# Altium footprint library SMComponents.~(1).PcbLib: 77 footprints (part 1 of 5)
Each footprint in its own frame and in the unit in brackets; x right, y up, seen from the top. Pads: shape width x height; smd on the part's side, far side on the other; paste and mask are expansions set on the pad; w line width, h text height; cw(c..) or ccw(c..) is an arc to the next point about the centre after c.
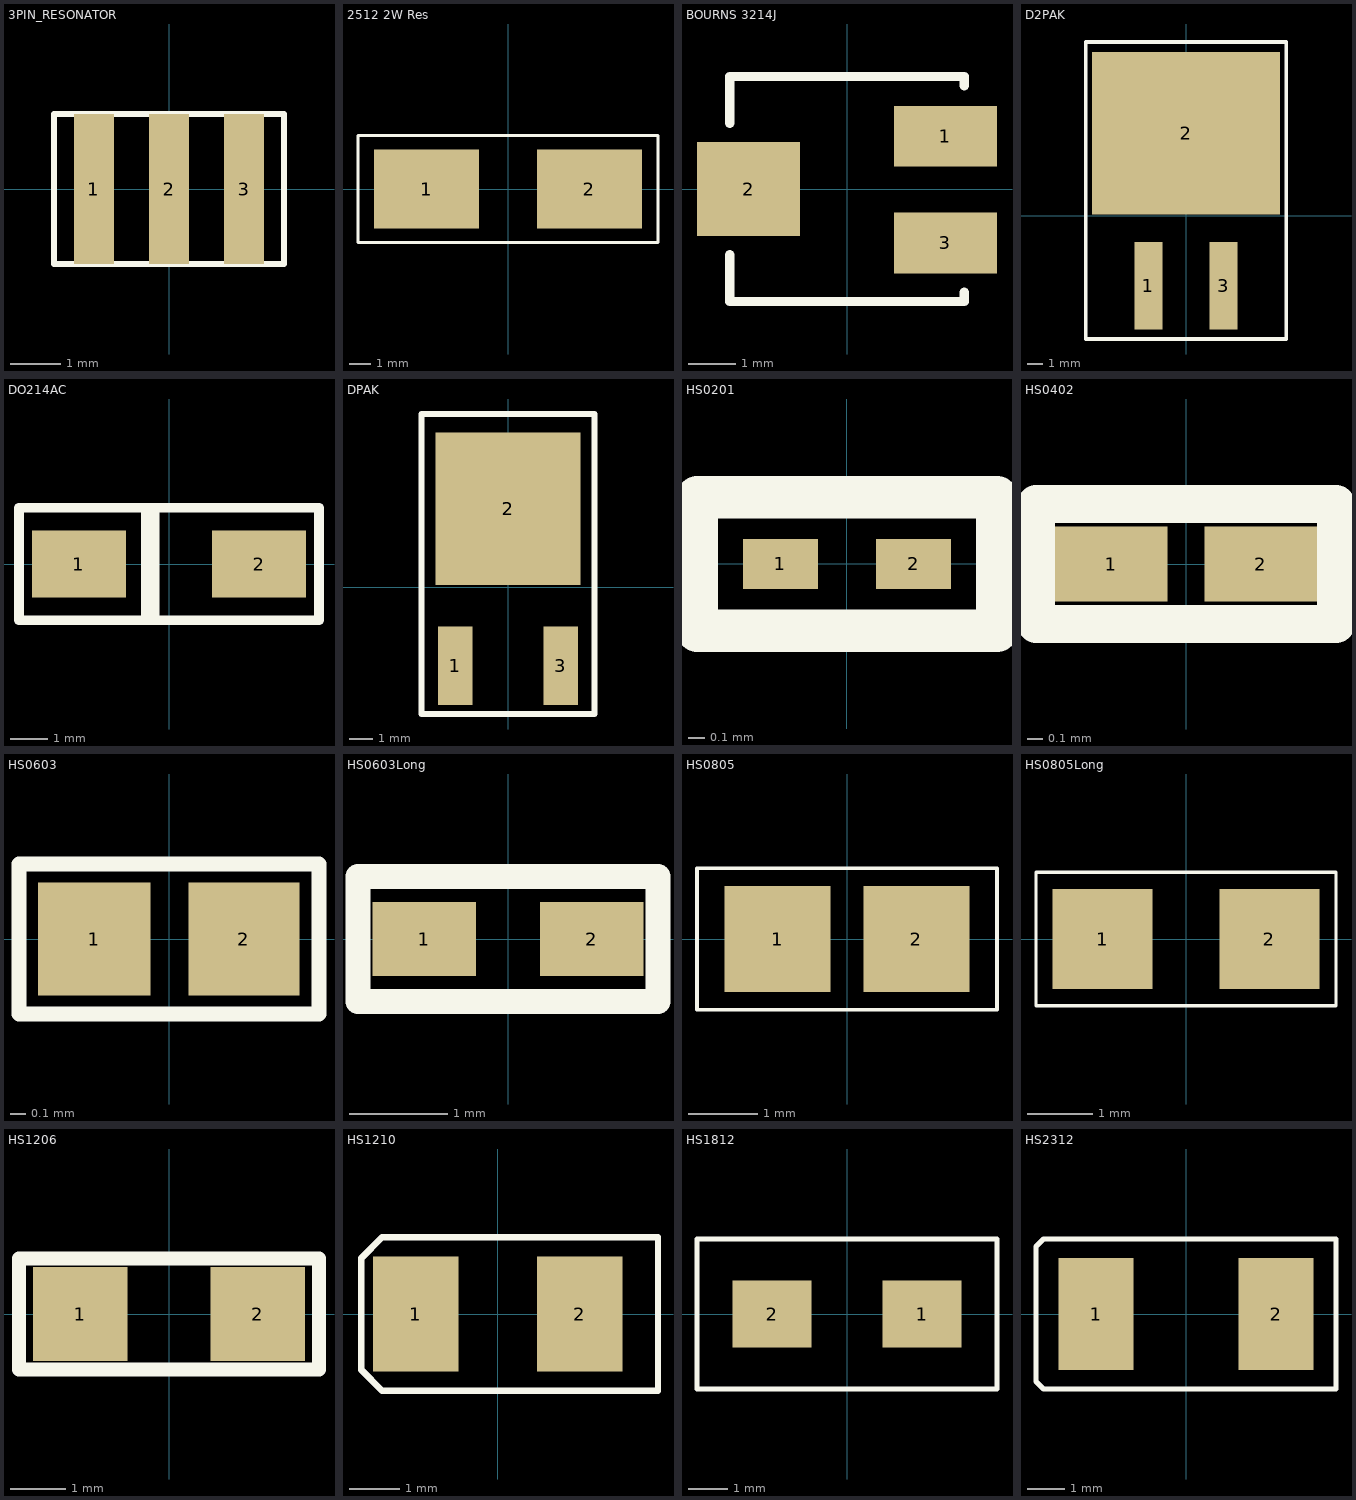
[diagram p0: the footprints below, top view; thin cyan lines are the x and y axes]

## 3PIN_RESONATOR [mm] "Mutata 600 series"
height 1.2
pads (3):
  rect 0.8x3 smd: 1(-1.5,0) 2(0,0) 3(1.5,0)
Top Overlay:
  lines w0.127: -2.3,-1.5 2.3,-1.5 2.3,1.5 -2.3,1.5 -2.3,-1.5

## 2512 2W Res [mm] "2W power resistor"
height 1
pads (2):
  rect 4.9x3.7 smd: 1(-3.8,0) 2(3.8,0)
Top Overlay:
  lines w0.127: -7,-2.5 -7,2.5 7,2.5 7,-2.5 -7,-2.5

## BOURNS 3214J [mm] "Bourns 3214J sm trimpot"
pads (3):
  rect 2.2x1.3 smd: 1(2.1,1.125) 3(2.1,-1.15)
  rect 2.2x2 smd: 2(-2.1,0)
Top Overlay:
  lines w0.2: -2.5,-1.4 -2.5,-2.4 2.5,-2.4 2.5,-2.2 ; -2.5,1.4 -2.5,2.4 2.5,2.4 2.5,2.2

## D2PAK [mm] "D2PAK 3 terminal (Will also mount DPAK)"
height 4
pads (3):
  rect 1.81x5.675 smd: 1(-2.435,-4.537) 3(2.435,-4.537)
  rect 12.2x10.525 smd: 2(0,5.35)
Top Overlay:
  lines w0.254: -6.5,-8 6.5,-8 6.5,11.25 -6.5,11.25 -6.5,-8

## DO214AC [mm] "DO214AC"
height 2.3
pads (2):
  rect 2.5x1.8 smd: 1(-2.4,0) 2(2.4,0)
Top Overlay:
  lines w0.254: -4,-1.5 -4,1.5 4,1.5 4,-1.5 -4,-1.5
  lines w0.5: -0.5,-1.35 -0.5,1.35

## DPAK [mm] "DPAK 3 terminal"
height 4
pads (3):
  rect 1.5x3.4 smd: 1(-2.286,-3.4) 3(2.286,-3.4)
  rect 6.3x6.6 smd: 2(0,3.4)
Top Overlay:
  lines w0.254: -3.75,-5.5 3.75,-5.5 3.75,7.5 -3.75,7.5 -3.75,-5.5

## HS0201 [mm] "Pack up and go home!"
pads (2):
  rect 0.45x0.3 smd: 1(-0.4,0) 2(0.4,0)
Top Overlay:
  lines w0.254: -0.9,-0.4 0.9,-0.4 0.9,-0.2 0.9,0.2 0.9,0.4 -0.9,0.4 -0.9,-0.4

## HS0402 [mm] "Far too small"
pads (2):
  rect 0.75x0.5 smd: 1(-0.5,0) 2(0.5,0)
Top Overlay:
  lines w0.254: -1,-0.4 1,-0.4 1,0.4 -1,0.4 -1,-0.4

## HS0603 [mm] "0603 for hand soldering"
height 0.5
pads (2):
  rect 0.75x0.75 smd: 1(-0.5,0)
  rect 0.74x0.75 smd: 2(0.5,0)
Top Overlay:
  lines w0.1: -1,-0.5 -1,0.5 1,0.5 1,-0.5 -1,-0.5

## HS0603Long [mm] "0603 for hand soldering"
height 0.5
pads (2):
  rect 1.05x0.75 smd: 1(-0.85,0) 2(0.85,0)
Top Overlay:
  lines w0.254: -1.524,-0.635 1.524,-0.635 1.524,0.635 -1.524,0.635 -1.524,-0.635

## HS0805 [mil] "0805 on big pads for hand soldering"
height 39.37
pads (2):
  rect 60x60 smd: 1(-39.37,0) 2(39.37,0)
Top Overlay:
  lines w2: -85,-40 85,-40 85,40 -85,40 -85,-40

## HS0805Long [mil] "0805 on big pads for hand soldering will also take 1206"
height 39.37
pads (2):
  rect 60x60 smd: 1(-50,0) 2(50,0)
Top Overlay:
  lines w2: -90,-40 -90,40 90,40 90,-40 -90,-40

## HS1206 [mm] "1206"
height 1.9
pads (2):
  rect 1.7x1.7 smd: 1(-1.6,0) 2(1.6,0)
Top Overlay:
  lines w0.254: -2.7,-1 -2.7,1 2.7,1 2.7,-1 -2.7,-1

## HS1210 [mm] "Tant case B (A will also fit!)"
height 1.9
pads (2):
  rect 1.7x2.286 smd: 1(-1.625,0) 2(1.626,0)
Top Overlay:
  lines w0.127: -2.7,-1.11 -2.286,-1.524 3.175,-1.524 3.175,1.524 -2.286,1.524 -2.7,1.11 -2.7,-1.11

## HS1812 [mm] "1812 footprint (inductors and big Rs)"
height 4
pads (2):
  rect 2x1.7 smd: 1(1.905,0) 2(-1.905,0)
Top Overlay:
  lines w0.127: -3.81,-1.905 3.81,-1.905 3.81,1.905 -3.81,1.905 -3.81,-1.905

## HS2312 [mm] "2312 footprint eg Tant case C"
height 2.6
pads (2):
  rect 2x3 smd: 1(-2.4,0) 2(2.4,0)
Top Overlay:
  lines w0.127: -4,-1.8 -4,1.8 -3.8,2 4,2 4,-2 -3.8,-2 -4,-1.8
